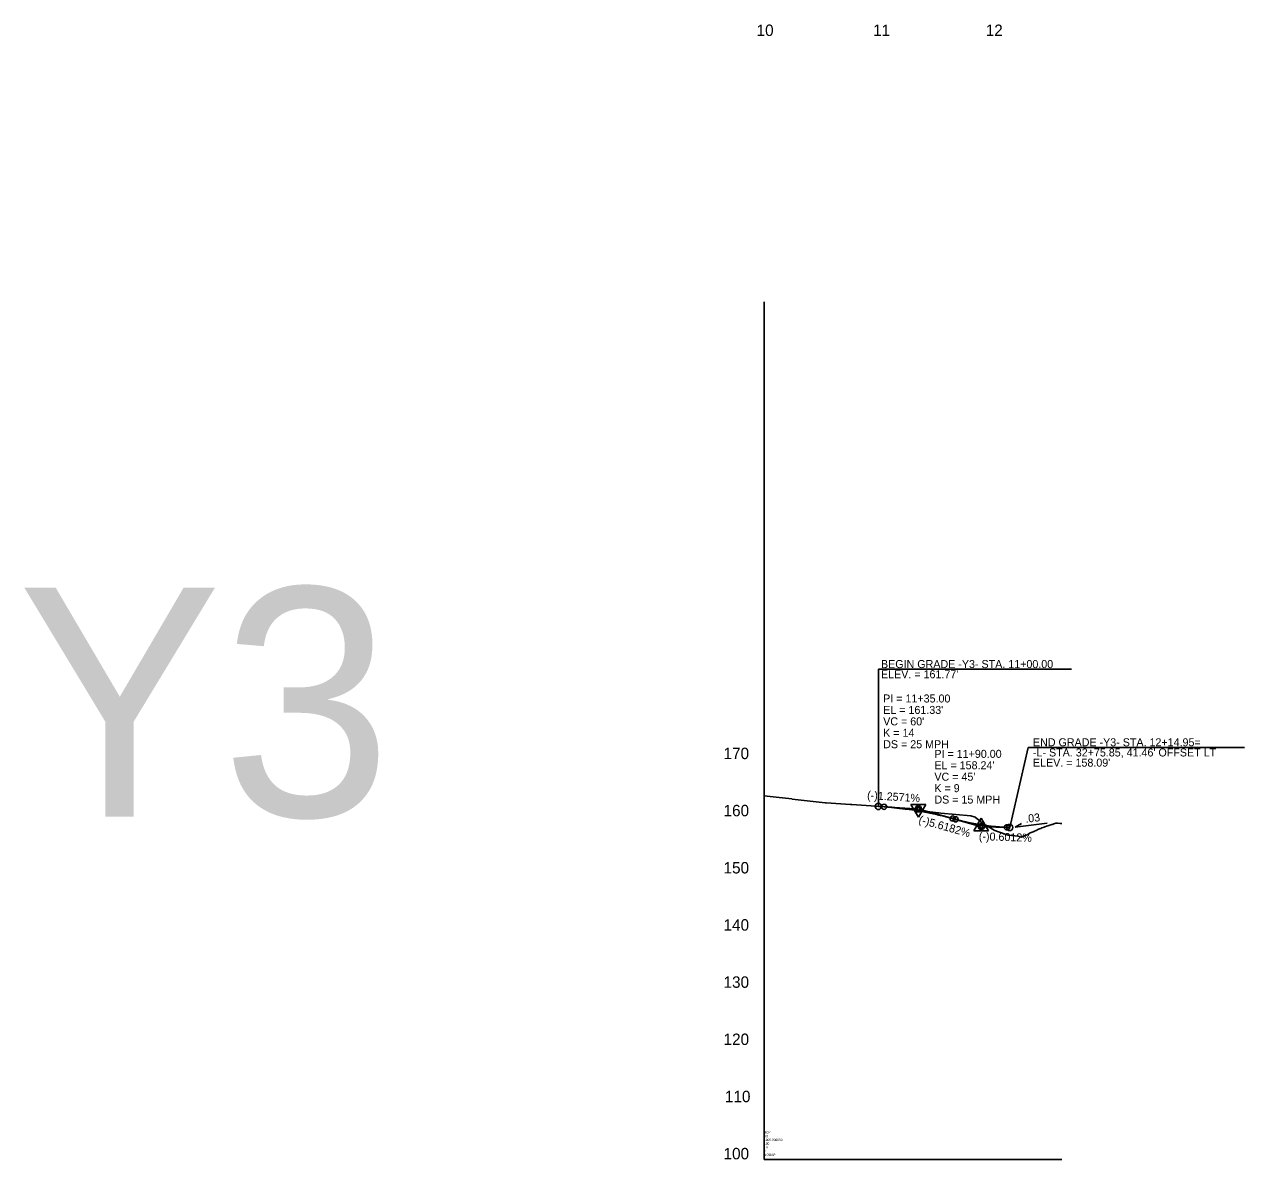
# Model space of a CAD drawing. Extents: x 1778432 to 1784301, y 601022 to 621789.
# Drawn here: x 1779496 to 1780563, y 615039 to 616032 of the extents above; entities that cross this region are included whole.
import ezdxf

# ---------------------------------------------------------------- set-up
doc = ezdxf.new("R2010")
doc.units = 0
for name, color, linetype in [('Exist Profile Cell', 7, 'Continuous'), ('Exist Vertical Profile Ground Line', 7, 'Continuous'), ('Exist Vertical Profile Horizontal Axis Label Major', 7, 'Continuous'), ('Exist Vertical Profile Vertical Axis Label', 7, 'Continuous'), ('Prop PFL Text', 7, 'Continuous'), ('Prop PFL VPI Symbol CELL', 7, 'Continuous'), ('Prop Vertical Profile Curve Label', 7, 'Continuous'), ('Prop Vertical Profile Grade', 7, 'Continuous'), ('Prop Vertical Profile Grade Label', 7, 'Continuous'), ('Prop VPI Label', 7, 'Continuous')]:
    doc.layers.add(name, color=color, linetype=linetype)

msp = doc.modelspace()

# ---------------------------------------------------------------- linework, layer by layer
at = {"layer": 'Exist Profile Cell'}
for q in [(1780143, 615789.2), (1780403.6, 615039.2), (1780143, 615039.2)]:
    msp.add_line((1780143, 615039.2), q, dxfattribs=at)
at = {"layer": 'Exist Vertical Profile Ground Line'}
msp.add_lwpolyline([(1780143.1, 615357.2), (1780153.5, 615356.1), (1780167.3, 615354.6), (1780167.7, 615354.5), (1780196.6, 615351.3), (1780197.4, 615351.2), (1780218.7, 615349.7), (1780219.7, 615349.7), (1780249.1, 615347.6), (1780249.6, 615347.6), (1780266.3, 615345.7), (1780267.7, 615345.5), (1780295.5, 615342.4), (1780297.6, 615342.1), (1780323.8, 615339.8), (1780327.8, 615338.6), (1780334, 615333.4), (1780344.4, 615327.2), (1780345, 615327), (1780347.3, 615326.1), (1780356.5, 615322.9), (1780365.2, 615321.9), (1780366.7, 615321.4), (1780368.4, 615321.1), (1780368.8, 615321.4), (1780369.3, 615321.6), (1780369.6, 615321.8), (1780370.4, 615322.1), (1780370.8, 615322.3), (1780373.6, 615323.6), (1780375.9, 615324.8), (1780377.6, 615325.5), (1780378.5, 615325.9), (1780379.7, 615326.5), (1780381, 615327), (1780383.2, 615328), (1780383.9, 615328.3), (1780385, 615328.7), (1780386.1, 615329.2), (1780388, 615329.9), (1780388.7, 615330.2), (1780390.1, 615330.7), (1780391.3, 615331.1), (1780393, 615331.7), (1780393.8, 615332), (1780394.7, 615332.2), (1780395.3, 615332.4), (1780395.6, 615332.2), (1780396.5, 615332.9), (1780398.1, 615333.3), (1780399.7, 615333.3), (1780402, 615333.2), (1780403.6, 615333.2)], dxfattribs=at)
at = {"layer": 'Prop PFL VPI Symbol CELL'}
for p, q in [((1780278, 615338.5), (1780271.5, 615349.7)), ((1780284.5, 615349.7), (1780271.5, 615349.7)), ((1780278, 615338.5), (1780284.5, 615349.7)), ((1780332.9, 615337.8), (1780326.5, 615326.6)), ((1780332.9, 615337.8), (1780339.4, 615326.6)), ((1780326.5, 615326.6), (1780339.4, 615326.6))]:
    msp.add_line(p, q, dxfattribs=at)
for centre, radius in [((1780278, 615346), 1.75), ((1780278, 615346), 1.2), ((1780332.9, 615330.3), 1.75), ((1780332.9, 615330.3), 1.2)]:
    msp.add_circle(centre, radius, dxfattribs=at)
at = {"layer": 'Prop Vertical Profile Curve Label'}
for centre in [(1780248, 615347.7), (1780308, 615337.4), (1780310.5, 615336.7), (1780355.5, 615329.7)]:
    msp.add_circle(centre, 2.25, dxfattribs=at)
at = {"layer": 'Prop Vertical Profile Grade'}
for p, q in [((1780243, 615348), (1780248, 615347.7)), ((1780308, 615337.4), (1780310.5, 615336.7)), ((1780355.5, 615329.7), (1780357.9, 615329.6))]:
    msp.add_line(p, q, dxfattribs=at)
for points in [[(1780248, 615347.7), (1780249.2, 615347.6), (1780250.4, 615347.6), (1780251.6, 615347.5), (1780252.8, 615347.4), (1780254, 615347.3), (1780255.2, 615347.2), (1780256.4, 615347.1), (1780257.6, 615346.9), (1780258.8, 615346.8), (1780260, 615346.7), (1780261.2, 615346.6), (1780262.4, 615346.4), (1780263.6, 615346.3), (1780264.8, 615346.2), (1780266, 615346), (1780267.2, 615345.9), (1780268.4, 615345.7), (1780269.6, 615345.5), (1780270.8, 615345.4), (1780272, 615345.2), (1780273.2, 615345), (1780274.4, 615344.8), (1780275.6, 615344.6), (1780276.8, 615344.4), (1780278, 615344.2), (1780279.2, 615344), (1780280.4, 615343.8), (1780281.6, 615343.6), (1780282.8, 615343.3), (1780284, 615343.1), (1780285.2, 615342.9), (1780286.4, 615342.6), (1780287.6, 615342.4), (1780288.8, 615342.1), (1780290, 615341.9), (1780291.2, 615341.6), (1780292.4, 615341.4), (1780293.6, 615341.1), (1780294.8, 615340.8), (1780296, 615340.5), (1780297.2, 615340.2), (1780298.4, 615340), (1780299.6, 615339.7), (1780300.8, 615339.4), (1780302, 615339), (1780303.2, 615338.7), (1780304.4, 615338.4), (1780305.6, 615338.1), (1780306.8, 615337.8), (1780308, 615337.4)], [(1780310.5, 615336.7), (1780311.4, 615336.5), (1780312.3, 615336.2), (1780313.2, 615336), (1780314.1, 615335.7), (1780315, 615335.5), (1780315.9, 615335.3), (1780316.8, 615335.1), (1780317.7, 615334.8), (1780318.6, 615334.6), (1780319.5, 615334.4), (1780320.4, 615334.2), (1780321.3, 615334), (1780322.2, 615333.8), (1780323.1, 615333.6), (1780324, 615333.4), (1780324.9, 615333.3), (1780325.8, 615333.1), (1780326.7, 615332.9), (1780327.6, 615332.7), (1780328.5, 615332.6), (1780329.4, 615332.4), (1780330.3, 615332.3), (1780331.2, 615332.1), (1780332.1, 615332), (1780333, 615331.8), (1780333.9, 615331.7), (1780334.8, 615331.5), (1780335.7, 615331.4), (1780336.6, 615331.3), (1780337.5, 615331.2), (1780338.4, 615331.1), (1780339.3, 615330.9), (1780340.2, 615330.8), (1780341.1, 615330.7), (1780342, 615330.6), (1780342.9, 615330.5), (1780343.8, 615330.5), (1780344.7, 615330.4), (1780345.6, 615330.3), (1780346.5, 615330.2), (1780347.4, 615330.1), (1780348.3, 615330.1), (1780349.2, 615330), (1780350.1, 615330), (1780351, 615329.9), (1780351.9, 615329.9), (1780352.8, 615329.8), (1780353.7, 615329.8), (1780354.6, 615329.7), (1780355.5, 615329.7)]]:
    msp.add_spline(points, degree=3, dxfattribs=at)
at = {"layer": 'Prop VPI Label'}
for p, q in [((1780243, 615348), (1780243, 615468)), ((1780243, 615468), (1780411.9, 615468)), ((1780357.9, 615329.6), (1780373.9, 615399.5)), ((1780373.9, 615399.5), (1780563.3, 615399.5)), ((1780248, 615347.7), (1780275.2, 615346)), ((1780308, 615337.4), (1780280.6, 615345.1)), ((1780310.5, 615336.7), (1780330.3, 615331.1)), ((1780355.5, 615329.7), (1780335.7, 615330.3)), ((1780362.6, 615330), (1780390.6, 615333.5)), ((1780362.6, 615330), (1780368.3, 615333.2))]:
    msp.add_line(p, q, dxfattribs=at)
for centre in [(1780243, 615348), (1780278, 615345.9), (1780333, 615330.4), (1780357.9, 615329.6)]:
    msp.add_circle(centre, 2.75, dxfattribs=at)

# ---------------------------------------------------------------- texts
at = {"layer": 'Exist Profile Cell'}
for s, p in [('Y3', (1780143, 615058.7)), ('RDY', (1780143, 615061.9)), ('1000.000000', (1780143, 615055.4)), ('100', (1780143, 615052.2)), ('10', (1780143, 615048.9)), ('2', (1780143, 615045.7)), ('NOGAP', (1780143, 615042.4))]:
    msp.add_text(s, height=2, dxfattribs=at).set_placement(p)
at = {"layer": 'Exist Vertical Profile Horizontal Axis Label Major'}
for s, p in [('10', (1780136.5, 616021.7)), ('11', (1780238.4, 616021.7)), ('12', (1780336.9, 616021.7))]:
    msp.add_text(s, height=10, dxfattribs=at).set_placement(p)
at = {"layer": 'Exist Vertical Profile Vertical Axis Label'}
for s, p in [('170', (1780107.6, 615389.4)), ('160', (1780107.6, 615339.4)), ('150', (1780107.6, 615289.4)), ('140', (1780107.6, 615239.4)), ('130', (1780107.6, 615189.4)), ('120', (1780107.6, 615139.4)), ('110', (1780108.8, 615089.4)), ('100', (1780107.6, 615039.4))]:
    msp.add_text(s, height=10, dxfattribs=at).set_placement(p)
at = {"layer": 'Prop PFL Text'}
msp.add_text('Y3', height=200, dxfattribs=at).set_placement((1779490.2, 615339.2))
at = {"layer": 'Prop Vertical Profile Curve Label'}
for s, p in [("VC = 60'", (1780247.2, 615418.9)), ('K = 14', (1780247.2, 615408.9)), ('DS = 25 MPH', (1780247.2, 615398.9)), ("VC = 45'", (1780292, 615370.5)), ('K = 9', (1780292, 615360.5)), ('DS = 15 MPH', (1780292, 615350.5))]:
    msp.add_text(s, height=7, dxfattribs=at).set_placement(p)
at = {"layer": 'Prop Vertical Profile Grade Label'}
for s, rotation, p in [('(-)1.2571%', 356.4641, (1780233, 615354.5)), ('(-)5.6182%', 344.3053, (1780277.7, 615333.5)), ('.03', 7.125, (1780371.9, 615333.6)), ('(-)0.6012%', 358.2531, (1780330.8, 615318.5))]:
    msp.add_text(s, height=7, rotation=rotation, dxfattribs=at).set_placement(p)
at = {"layer": 'Prop VPI Label'}
for s, p in [('BEGIN GRADE -Y3- STA. 11+00.00', (1780245.3, 615469)), ("ELEV. = 161.77'", (1780245.3, 615460.1)), ('PI = 11+35.00', (1780247.2, 615438.9)), ("EL = 161.33'", (1780247.2, 615428.9)), ('END GRADE -Y3- STA. 12+14.95=', (1780378.2, 615400.6)), ('PI = 11+90.00', (1780292, 615390.5)), ("-L- STA. 32+75.85, 41.46' OFFSET LT", (1780378.2, 615391.7)), ("ELEV. = 158.09'", (1780378.2, 615382.8)), ("EL = 158.24'", (1780292, 615380.5))]:
    msp.add_text(s, height=7, dxfattribs=at).set_placement(p)

doc.saveas('drawing.dxf')
